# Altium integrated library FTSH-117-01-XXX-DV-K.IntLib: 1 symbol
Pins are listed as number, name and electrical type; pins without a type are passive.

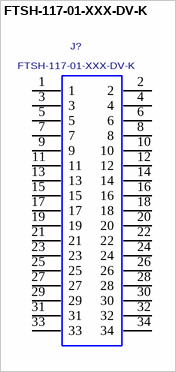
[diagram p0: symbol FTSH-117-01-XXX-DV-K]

## FTSH-117-01-XXX-DV-K
designator J?
0.050 INCH DOUBLE VERTICAL SMT TERMINAL STIP.; MANUFACTURER: SAMTEC
footprint FTSH-117-01-XXX-DV-K
pins: 1, 2, 3, 4, 5, 6, 7, 8, 9, 10, 11, 12, 13, 14, 15, 16, 17, 18, 19, 20, 21, 22, 23, 24, 25, 26, 27, 28, 29, 30, 31, 32, 33, 34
